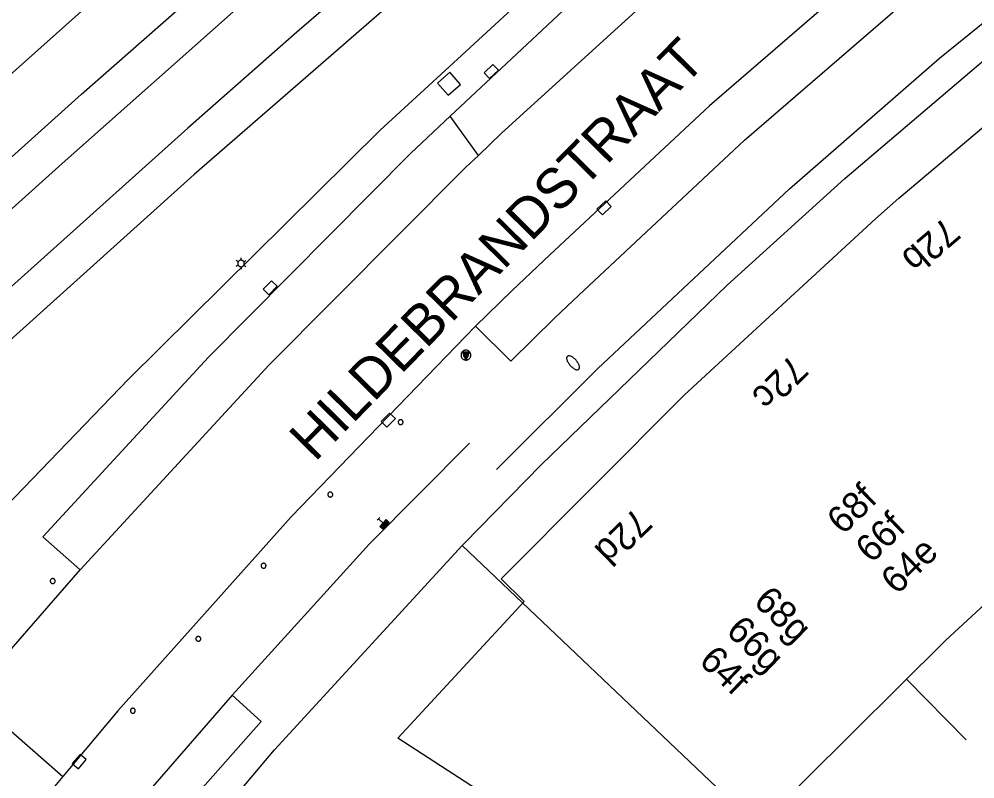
# Model space of a CAD drawing. Extents: x 81065 to 81486, y 452384 to 452681.
# Drawn here: x 81125.76 to 81161.34, y 452398.58 to 452426.85 of the extents above; entities that cross this region are included whole.
import ezdxf

# ---------------------------------------------------------------- set-up
doc = ezdxf.new("R2010")
doc.units = 0
for name, color, linetype in [('B-BH-AL-TOPOGRAFIE_HUISNUMMER-T25', 7, 'Continuous'), ('B-BH-AL-TOPOGRAFIE_STRAATNAAM-S', 7, 'Continuous'), ('B-BH-IE-MEUBILAIR-WEGMEUBILAIR-VERKEERSBORD-S', 7, 'Continuous'), ('B-BH-IE-MEUBILAIR_WEGMEUBILAIR_LICHTMAST-S', 7, 'Continuous'), ('B-BH-IE-MEUBILAIR_WEGMEUBILAIR_PAAL-S', 7, 'Continuous'), ('B-BH-KL-DATA_CAI_KAST-S', 7, 'Continuous'), ('B-BH-KL-WATER_BRANDLEIDING_PUT-S', 7, 'Continuous'), ('B-BH-OG-TERREIN_ERF-GV', 7, 'Continuous'), ('B-BH-OG-TOPOGRAFIE_BEBOUWING-GV', 7, 'Continuous'), ('B-BH-OG-TOPOGRAFIE_BEBOUWING_PANDSCHEIDING-GV', 7, 'Continuous'), ('B-BH-RI-GWA_RIOOLPUT-S', 7, 'Continuous'), ('B-BH-VH-KANTOPSLUITING-GV', 7, 'Continuous'), ('B-SB-OG-WEG_SPOOR_TRAM-G', 7, 'Continuous'), ('B-SRI-KOLK_COMBINATIE-S', 7, 'Continuous')]:
    doc.layers.add(name, color=color, linetype=linetype)

msp = doc.modelspace()

# ---------------------------------------------------------------- linework, layer by layer
at = {"layer": 'B-BH-IE-MEUBILAIR-WEGMEUBILAIR-VERKEERSBORD-S'}
for p, q in [((81142.26, 452414.473), (81142.525, 452414.473)), ((81142.393, 452414.164), (81142.282, 452414.455)), ((81142.282, 452414.455), (81142.498, 452414.455)), ((81142.309, 452414.437), (81142.47, 452414.437)), ((81142.394, 452414.213), (81142.309, 452414.437)), ((81142.395, 452414.262), (81142.335, 452414.418)), ((81142.335, 452414.418), (81142.442, 452414.418)), ((81142.396, 452414.311), (81142.362, 452414.4)), ((81142.362, 452414.4), (81142.414, 452414.4)), ((81142.397, 452414.359), (81142.388, 452414.382)), ((81142.525, 452414.473), (81142.393, 452414.164)), ((81142.498, 452414.455), (81142.394, 452414.213)), ((81142.47, 452414.437), (81142.395, 452414.262)), ((81142.442, 452414.418), (81142.396, 452414.311)), ((81142.414, 452414.4), (81142.397, 452414.359))]:
    msp.add_line(p, q, dxfattribs=at)
msp.add_lwpolyline([(81142.21, 452414.347), (81142.211, 452414.328), (81142.214, 452414.309), (81142.219, 452414.29), (81142.226, 452414.272), (81142.234, 452414.255), (81142.245, 452414.239), (81142.257, 452414.224), (81142.27, 452414.211), (81142.285, 452414.199), (81142.301, 452414.188), (81142.318, 452414.18), (81142.336, 452414.173), (81142.355, 452414.168), (81142.374, 452414.165), (81142.393, 452414.164), (81142.412, 452414.165), (81142.431, 452414.168), (81142.45, 452414.173), (81142.467, 452414.18), (81142.484, 452414.188), (81142.501, 452414.199), (81142.515, 452414.211), (81142.529, 452414.224), (81142.541, 452414.239), (81142.551, 452414.255), (81142.56, 452414.272), (81142.567, 452414.29), (81142.572, 452414.309), (81142.575, 452414.328), (81142.576, 452414.347), (81142.575, 452414.366), (81142.572, 452414.385), (81142.567, 452414.404), (81142.56, 452414.421), (81142.551, 452414.438), (81142.541, 452414.455), (81142.529, 452414.469), (81142.515, 452414.483), (81142.501, 452414.495), (81142.484, 452414.505), (81142.467, 452414.514), (81142.45, 452414.521), (81142.431, 452414.526), (81142.412, 452414.529), (81142.393, 452414.53), (81142.374, 452414.529), (81142.355, 452414.526), (81142.336, 452414.521), (81142.318, 452414.514), (81142.301, 452414.505), (81142.285, 452414.495), (81142.27, 452414.483), (81142.257, 452414.469), (81142.245, 452414.455), (81142.234, 452414.438), (81142.226, 452414.421), (81142.219, 452414.404), (81142.214, 452414.385), (81142.211, 452414.366), (81142.21, 452414.347)], dxfattribs=at)
at = {"layer": 'B-BH-IE-MEUBILAIR_WEGMEUBILAIR_LICHTMAST-S'}
for p, q in [((81133.915, 452417.818), (81133.836, 452417.864)), ((81134.021, 452417.879), (81134.021, 452417.971)), ((81134.126, 452417.818), (81134.206, 452417.864)), ((81133.915, 452417.696), (81133.836, 452417.65)), ((81134.021, 452417.635), (81134.021, 452417.543)), ((81134.126, 452417.696), (81134.206, 452417.65))]:
    msp.add_line(p, q, dxfattribs=at)
msp.add_lwpolyline([(81133.899, 452417.757), (81133.9, 452417.744), (81133.901, 452417.731), (81133.905, 452417.719), (81133.909, 452417.707), (81133.915, 452417.696), (81133.922, 452417.685), (81133.93, 452417.675), (81133.939, 452417.666), (81133.949, 452417.658), (81133.96, 452417.651), (81133.971, 452417.645), (81133.983, 452417.641), (81133.996, 452417.637), (81134.008, 452417.636), (81134.021, 452417.635), (81134.034, 452417.636), (81134.046, 452417.637), (81134.059, 452417.641), (81134.071, 452417.645), (81134.082, 452417.651), (81134.093, 452417.658), (81134.103, 452417.666), (81134.112, 452417.675), (81134.12, 452417.685), (81134.127, 452417.696), (81134.132, 452417.707), (81134.137, 452417.719), (81134.14, 452417.731), (81134.142, 452417.744), (81134.143, 452417.757), (81134.142, 452417.77), (81134.14, 452417.782), (81134.137, 452417.795), (81134.132, 452417.807), (81134.127, 452417.818), (81134.12, 452417.829), (81134.112, 452417.839), (81134.103, 452417.848), (81134.093, 452417.856), (81134.082, 452417.863), (81134.071, 452417.868), (81134.059, 452417.873), (81134.046, 452417.876), (81134.034, 452417.878), (81134.021, 452417.879), (81134.008, 452417.878), (81133.995, 452417.876), (81133.983, 452417.873), (81133.971, 452417.868), (81133.96, 452417.863), (81133.949, 452417.856), (81133.939, 452417.848), (81133.93, 452417.839), (81133.922, 452417.829), (81133.915, 452417.818), (81133.909, 452417.807), (81133.905, 452417.795), (81133.901, 452417.782), (81133.9, 452417.77), (81133.899, 452417.757)], dxfattribs=at)
at = {"layer": 'B-BH-IE-MEUBILAIR_WEGMEUBILAIR_PAAL-S'}
for points in [[(81142.301, 452414.347), (81142.302, 452414.337), (81142.303, 452414.328), (81142.306, 452414.318), (81142.309, 452414.309), (81142.313, 452414.301), (81142.319, 452414.293), (81142.325, 452414.285), (81142.331, 452414.279), (81142.339, 452414.273), (81142.347, 452414.267), (81142.356, 452414.263), (81142.364, 452414.26), (81142.374, 452414.257), (81142.383, 452414.256), (81142.393, 452414.255), (81142.402, 452414.256), (81142.412, 452414.257), (81142.421, 452414.26), (81142.43, 452414.263), (81142.439, 452414.267), (81142.447, 452414.273), (81142.454, 452414.279), (81142.461, 452414.285), (81142.467, 452414.293), (81142.472, 452414.301), (81142.476, 452414.309), (81142.48, 452414.318), (81142.482, 452414.328), (81142.484, 452414.337), (81142.484, 452414.347), (81142.484, 452414.356), (81142.482, 452414.366), (81142.48, 452414.375), (81142.476, 452414.384), (81142.472, 452414.392), (81142.467, 452414.4), (81142.461, 452414.408), (81142.454, 452414.415), (81142.447, 452414.421), (81142.439, 452414.426), (81142.43, 452414.43), (81142.421, 452414.434), (81142.412, 452414.436), (81142.402, 452414.438), (81142.393, 452414.438), (81142.383, 452414.438), (81142.374, 452414.436), (81142.364, 452414.434), (81142.356, 452414.43), (81142.347, 452414.426), (81142.339, 452414.421), (81142.331, 452414.415), (81142.325, 452414.408), (81142.319, 452414.4), (81142.313, 452414.392), (81142.309, 452414.384), (81142.306, 452414.375), (81142.303, 452414.366), (81142.302, 452414.356), (81142.301, 452414.347)], [(81139.871, 452411.854), (81139.872, 452411.844), (81139.873, 452411.835), (81139.876, 452411.825), (81139.879, 452411.816), (81139.883, 452411.808), (81139.889, 452411.8), (81139.895, 452411.792), (81139.901, 452411.786), (81139.909, 452411.78), (81139.917, 452411.774), (81139.926, 452411.77), (81139.934, 452411.767), (81139.944, 452411.764), (81139.953, 452411.763), (81139.963, 452411.762), (81139.972, 452411.763), (81139.982, 452411.764), (81139.991, 452411.767), (81140, 452411.77), (81140.009, 452411.774), (81140.017, 452411.78), (81140.024, 452411.786), (81140.031, 452411.792), (81140.037, 452411.8), (81140.042, 452411.808), (81140.046, 452411.816), (81140.05, 452411.825), (81140.052, 452411.835), (81140.054, 452411.844), (81140.054, 452411.854), (81140.054, 452411.863), (81140.052, 452411.873), (81140.05, 452411.882), (81140.046, 452411.891), (81140.042, 452411.899), (81140.037, 452411.907), (81140.031, 452411.915), (81140.024, 452411.922), (81140.017, 452411.928), (81140.009, 452411.933), (81140, 452411.937), (81139.991, 452411.941), (81139.982, 452411.943), (81139.972, 452411.945), (81139.963, 452411.945), (81139.953, 452411.945), (81139.944, 452411.943), (81139.934, 452411.941), (81139.926, 452411.937), (81139.917, 452411.933), (81139.909, 452411.928), (81139.901, 452411.922), (81139.895, 452411.915), (81139.889, 452411.907), (81139.883, 452411.899), (81139.879, 452411.891), (81139.876, 452411.882), (81139.873, 452411.873), (81139.872, 452411.863), (81139.871, 452411.854)], [(81137.252, 452409.158), (81137.253, 452409.148), (81137.254, 452409.139), (81137.257, 452409.129), (81137.26, 452409.12), (81137.264, 452409.112), (81137.27, 452409.104), (81137.276, 452409.096), (81137.282, 452409.09), (81137.29, 452409.084), (81137.298, 452409.078), (81137.307, 452409.074), (81137.315, 452409.071), (81137.325, 452409.068), (81137.334, 452409.067), (81137.344, 452409.066), (81137.353, 452409.067), (81137.363, 452409.068), (81137.372, 452409.071), (81137.381, 452409.074), (81137.39, 452409.078), (81137.398, 452409.084), (81137.405, 452409.09), (81137.412, 452409.096), (81137.418, 452409.104), (81137.423, 452409.112), (81137.427, 452409.12), (81137.431, 452409.129), (81137.433, 452409.139), (81137.435, 452409.148), (81137.435, 452409.158), (81137.435, 452409.167), (81137.433, 452409.177), (81137.431, 452409.186), (81137.427, 452409.195), (81137.423, 452409.203), (81137.418, 452409.211), (81137.412, 452409.219), (81137.405, 452409.226), (81137.398, 452409.232), (81137.39, 452409.237), (81137.381, 452409.241), (81137.372, 452409.245), (81137.363, 452409.247), (81137.353, 452409.249), (81137.344, 452409.249), (81137.334, 452409.249), (81137.325, 452409.247), (81137.315, 452409.245), (81137.307, 452409.241), (81137.298, 452409.237), (81137.29, 452409.232), (81137.282, 452409.226), (81137.276, 452409.219), (81137.27, 452409.211), (81137.264, 452409.203), (81137.26, 452409.195), (81137.257, 452409.186), (81137.254, 452409.177), (81137.253, 452409.167), (81137.252, 452409.158)], [(81134.769, 452406.511), (81134.77, 452406.501), (81134.771, 452406.492), (81134.774, 452406.482), (81134.777, 452406.473), (81134.781, 452406.465), (81134.787, 452406.457), (81134.793, 452406.449), (81134.799, 452406.443), (81134.807, 452406.437), (81134.815, 452406.431), (81134.824, 452406.427), (81134.832, 452406.424), (81134.842, 452406.421), (81134.851, 452406.42), (81134.861, 452406.419), (81134.87, 452406.42), (81134.88, 452406.421), (81134.889, 452406.424), (81134.898, 452406.427), (81134.907, 452406.431), (81134.915, 452406.437), (81134.922, 452406.443), (81134.929, 452406.449), (81134.935, 452406.457), (81134.94, 452406.465), (81134.944, 452406.473), (81134.948, 452406.482), (81134.95, 452406.492), (81134.952, 452406.501), (81134.952, 452406.511), (81134.952, 452406.52), (81134.95, 452406.53), (81134.948, 452406.539), (81134.944, 452406.548), (81134.94, 452406.556), (81134.935, 452406.564), (81134.929, 452406.572), (81134.922, 452406.579), (81134.915, 452406.585), (81134.907, 452406.59), (81134.898, 452406.594), (81134.889, 452406.598), (81134.88, 452406.6), (81134.87, 452406.602), (81134.861, 452406.602), (81134.851, 452406.602), (81134.842, 452406.6), (81134.832, 452406.598), (81134.824, 452406.594), (81134.815, 452406.59), (81134.807, 452406.585), (81134.799, 452406.579), (81134.793, 452406.572), (81134.787, 452406.564), (81134.781, 452406.556), (81134.777, 452406.548), (81134.774, 452406.539), (81134.771, 452406.53), (81134.77, 452406.52), (81134.769, 452406.511)], [(81126.92, 452405.939), (81126.921, 452405.929), (81126.922, 452405.92), (81126.925, 452405.91), (81126.928, 452405.901), (81126.932, 452405.893), (81126.938, 452405.885), (81126.944, 452405.877), (81126.95, 452405.871), (81126.958, 452405.865), (81126.966, 452405.859), (81126.975, 452405.855), (81126.983, 452405.852), (81126.993, 452405.849), (81127.002, 452405.848), (81127.012, 452405.847), (81127.021, 452405.848), (81127.031, 452405.849), (81127.04, 452405.852), (81127.049, 452405.855), (81127.058, 452405.859), (81127.066, 452405.865), (81127.073, 452405.871), (81127.08, 452405.877), (81127.086, 452405.885), (81127.091, 452405.893), (81127.095, 452405.901), (81127.099, 452405.91), (81127.101, 452405.92), (81127.103, 452405.929), (81127.103, 452405.939), (81127.103, 452405.948), (81127.101, 452405.958), (81127.099, 452405.967), (81127.095, 452405.976), (81127.091, 452405.984), (81127.086, 452405.992), (81127.08, 452406), (81127.073, 452406.007), (81127.066, 452406.013), (81127.058, 452406.018), (81127.049, 452406.022), (81127.04, 452406.026), (81127.031, 452406.028), (81127.021, 452406.03), (81127.012, 452406.03), (81127.002, 452406.03), (81126.993, 452406.028), (81126.983, 452406.026), (81126.975, 452406.022), (81126.966, 452406.018), (81126.958, 452406.013), (81126.95, 452406.007), (81126.944, 452406), (81126.938, 452405.992), (81126.932, 452405.984), (81126.928, 452405.976), (81126.925, 452405.967), (81126.922, 452405.958), (81126.921, 452405.948), (81126.92, 452405.939)], [(81132.34, 452403.79), (81132.341, 452403.78), (81132.342, 452403.771), (81132.345, 452403.761), (81132.348, 452403.752), (81132.352, 452403.744), (81132.358, 452403.736), (81132.364, 452403.728), (81132.37, 452403.722), (81132.378, 452403.716), (81132.386, 452403.71), (81132.395, 452403.706), (81132.403, 452403.703), (81132.413, 452403.7), (81132.422, 452403.699), (81132.432, 452403.698), (81132.441, 452403.699), (81132.451, 452403.7), (81132.46, 452403.703), (81132.469, 452403.706), (81132.478, 452403.71), (81132.486, 452403.716), (81132.493, 452403.722), (81132.5, 452403.728), (81132.506, 452403.736), (81132.511, 452403.744), (81132.515, 452403.752), (81132.519, 452403.761), (81132.521, 452403.771), (81132.523, 452403.78), (81132.523, 452403.79), (81132.523, 452403.799), (81132.521, 452403.809), (81132.519, 452403.818), (81132.515, 452403.827), (81132.511, 452403.835), (81132.506, 452403.843), (81132.5, 452403.851), (81132.493, 452403.858), (81132.486, 452403.864), (81132.478, 452403.869), (81132.469, 452403.873), (81132.46, 452403.877), (81132.451, 452403.879), (81132.441, 452403.881), (81132.432, 452403.881), (81132.422, 452403.881), (81132.413, 452403.879), (81132.403, 452403.877), (81132.395, 452403.873), (81132.386, 452403.869), (81132.378, 452403.864), (81132.37, 452403.858), (81132.364, 452403.851), (81132.358, 452403.843), (81132.352, 452403.835), (81132.348, 452403.827), (81132.345, 452403.818), (81132.342, 452403.809), (81132.341, 452403.799), (81132.34, 452403.79)], [(81129.903, 452401.112), (81129.904, 452401.102), (81129.905, 452401.093), (81129.908, 452401.083), (81129.911, 452401.074), (81129.915, 452401.066), (81129.921, 452401.058), (81129.927, 452401.05), (81129.933, 452401.044), (81129.941, 452401.038), (81129.949, 452401.032), (81129.958, 452401.028), (81129.966, 452401.025), (81129.976, 452401.022), (81129.985, 452401.021), (81129.995, 452401.02), (81130.004, 452401.021), (81130.014, 452401.022), (81130.023, 452401.025), (81130.032, 452401.028), (81130.041, 452401.032), (81130.049, 452401.038), (81130.056, 452401.044), (81130.063, 452401.05), (81130.069, 452401.058), (81130.074, 452401.066), (81130.078, 452401.074), (81130.082, 452401.083), (81130.084, 452401.093), (81130.086, 452401.102), (81130.086, 452401.112), (81130.086, 452401.121), (81130.084, 452401.131), (81130.082, 452401.14), (81130.078, 452401.149), (81130.074, 452401.157), (81130.069, 452401.165), (81130.063, 452401.173), (81130.056, 452401.18), (81130.049, 452401.186), (81130.041, 452401.191), (81130.032, 452401.195), (81130.023, 452401.199), (81130.014, 452401.201), (81130.004, 452401.203), (81129.995, 452401.203), (81129.985, 452401.203), (81129.976, 452401.201), (81129.966, 452401.199), (81129.958, 452401.195), (81129.949, 452401.191), (81129.941, 452401.186), (81129.933, 452401.18), (81129.927, 452401.173), (81129.921, 452401.165), (81129.915, 452401.157), (81129.911, 452401.149), (81129.908, 452401.14), (81129.905, 452401.131), (81129.904, 452401.121), (81129.903, 452401.112)]]:
    msp.add_lwpolyline(points, dxfattribs=at)
at = {"layer": 'B-BH-KL-DATA_CAI_KAST-S'}
for p, q in [((81139.094, 452408.199), (81139.188, 452408.3)), ((81139.142, 452408.25), (81139.308, 452408.095)), ((81139.189, 452407.967), (81139.427, 452408.224)), ((81139.22, 452407.964), (81139.433, 452408.194)), ((81139.427, 452408.224), (81139.537, 452408.123)), ((81139.433, 452408.194), (81139.506, 452408.127)), ((81139.299, 452407.866), (81139.189, 452407.967)), ((81139.293, 452407.896), (81139.22, 452407.964)), ((81139.251, 452407.96), (81139.439, 452408.164)), ((81139.288, 452407.927), (81139.251, 452407.96)), ((81139.282, 452407.957), (81139.445, 452408.134)), ((81139.288, 452407.927), (81139.475, 452408.13)), ((81139.293, 452407.896), (81139.506, 452408.127)), ((81139.537, 452408.123), (81139.299, 452407.866)), ((81139.439, 452408.164), (81139.475, 452408.13))]:
    msp.add_line(p, q, dxfattribs=at)
at = {"layer": 'B-BH-KL-WATER_BRANDLEIDING_PUT-S'}
msp.add_lwpolyline([(81146.49, 452414.157), (81146.467, 452414.182), (81146.443, 452414.205), (81146.419, 452414.227), (81146.394, 452414.247), (81146.369, 452414.265), (81146.344, 452414.28), (81146.32, 452414.294), (81146.296, 452414.304), (81146.273, 452414.312), (81146.251, 452414.318), (81146.231, 452414.32), (81146.212, 452414.32), (81146.196, 452414.316), (81146.181, 452414.31), (81146.168, 452414.302), (81146.158, 452414.29), (81146.15, 452414.276), (81146.145, 452414.26), (81146.142, 452414.242), (81146.142, 452414.221), (81146.145, 452414.199), (81146.15, 452414.175), (81146.157, 452414.15), (81146.167, 452414.124), (81146.18, 452414.098), (81146.194, 452414.071), (81146.211, 452414.044), (81146.23, 452414.017), (81146.25, 452413.99), (81146.271, 452413.965), (81146.294, 452413.94), (81146.318, 452413.917), (81146.342, 452413.895), (81146.367, 452413.875), (81146.392, 452413.857), (81146.417, 452413.841), (81146.442, 452413.828), (81146.466, 452413.818), (81146.488, 452413.81), (81146.51, 452413.804), (81146.53, 452413.802), (81146.549, 452413.802), (81146.566, 452413.806), (81146.581, 452413.812), (81146.593, 452413.82), (81146.603, 452413.832), (81146.611, 452413.846), (81146.616, 452413.862), (81146.619, 452413.88), (81146.619, 452413.901), (81146.617, 452413.923), (81146.612, 452413.947), (81146.604, 452413.972), (81146.594, 452413.997), (81146.581, 452414.024), (81146.567, 452414.051), (81146.55, 452414.078), (81146.532, 452414.105), (81146.511, 452414.132), (81146.49, 452414.157)], dxfattribs=at)
at = {"layer": 'B-BH-OG-TERREIN_ERF-GV'}
msp.add_line((81158.795, 452402.292), (81161.008, 452400.033), dxfattribs=at)
at = {"layer": 'B-BH-OG-TOPOGRAFIE_BEBOUWING-GV'}
for points in [[(81126.018, 452388.532), (81127.195, 452390.075), (81135.264, 452399.653), (81142.254, 452407.263), (81142.332, 452407.331), (81145.191, 452410.261), (81152.12, 452416.954), (81156.495, 452420.925), (81163.982, 452427.288), (81169.073, 452431.334), (81177.002, 452437.212), (81179.582, 452438.967)], [(81153.251, 452396.796), (81151.969, 452398.03), (81148.503, 452394.479), (81139.858, 452400.091), (81144.562, 452405.184), (81143.704, 452406.025), (81150.532, 452412.867), (81157.636, 452419.422), (81158.509, 452420.19), (81166.091, 452426.576), (81171.032, 452430.467), (81180.823, 452437.684), (81181.948, 452438.481)], [(81180.883, 452421.217), (81173.621, 452415.514), (81166.038, 452409.069), (81160.256, 452403.741), (81153.266, 452396.81), (81153.251, 452396.796)]]:
    msp.add_lwpolyline(points, dxfattribs=at)
at = {"layer": 'B-BH-OG-TOPOGRAFIE_BEBOUWING_PANDSCHEIDING-GV'}
msp.add_line((81142.254, 452407.263), (81151.969, 452398.03), dxfattribs=at)
at = {"layer": 'B-BH-RI-GWA_RIOOLPUT-S'}
for p, q in [((81141.792, 452424.873), (81141.334, 452424.474)), ((81142.19, 452424.415), (81141.792, 452424.873)), ((81141.334, 452424.474), (81141.732, 452424.016)), ((81141.732, 452424.016), (81142.19, 452424.415))]:
    msp.add_line(p, q, dxfattribs=at)
at = {"layer": 'B-BH-VH-KANTOPSLUITING-GV'}
for p, q in [((81131.086, 452429.833), (81124.643, 452424.084)), ((81142.857, 452421.78), (81141.808, 452423.239)), ((81123.96, 452401.661), (81127.389, 452398.664))]:
    msp.add_line(p, q, dxfattribs=at)
for points in [[(81140.996, 452424.369), (81146.104, 452429.072), (81153.228, 452435.084), (81161.305, 452441.447), (81162.668, 452442.441)], [(81164.068, 452442.154), (81163.029, 452441.387), (81154.74, 452434.776), (81153.97, 452434.135), (81146.004, 452427.162), (81141.808, 452423.239)], [(81142.857, 452421.78), (81143.721, 452422.609), (81151.159, 452429.38), (81158.861, 452435.849), (81160.95, 452437.516), (81166.505, 452441.653)], [(81172.398, 452440.443), (81167.9, 452437.209), (81160.559, 452431.438), (81159.067, 452430.202), (81151.454, 452423.628), (81145.52, 452418.076)], [(81146.597, 452416.577), (81152.757, 452422.352), (81160.08, 452428.668), (81160.699, 452429.18), (81168.493, 452435.353), (81174.802, 452439.949)], [(81143.534, 452410.094), (81147.299, 452413.851), (81154.435, 452420.535), (81160.019, 452425.401), (81167.617, 452431.556), (81172.763, 452435.453), (81178.135, 452439.264)], [(81117.537, 452400.177), (81119.063, 452401.963), (81125.277, 452408.727), (81129.835, 452413.447), (81139.202, 452422.718), (81140.996, 452424.369)], [(81141.808, 452423.239), (81140.341, 452421.868), (81132.815, 452414.269), (81126.639, 452407.585), (81128.031, 452406.358)], [(81128.031, 452406.358), (81135.062, 452413.979), (81142.381, 452421.324), (81142.857, 452421.78)], [(81145.52, 452418.076), (81144.109, 452416.756), (81142.75, 452415.423)], [(81142.75, 452415.423), (81144.064, 452414.123), (81145.701, 452415.738), (81146.597, 452416.577)], [(81142.75, 452415.423), (81135.885, 452408.332), (81129.439, 452401.115), (81127.389, 452398.664), (81123.349, 452393.832), (81121.926, 452391.977)], [(81133.697, 452401.686), (81138.809, 452407.323), (81142.531, 452411.075)], [(81118.394, 452394.815), (81120.717, 452397.671), (81124.301, 452402.08), (81128.031, 452406.358)], [(81133.697, 452401.686), (81130.407, 452397.904), (81131.452, 452396.961)], [(81131.452, 452396.961), (81134.766, 452400.715), (81133.697, 452401.686)]]:
    msp.add_lwpolyline(points, dxfattribs=at)
at = {"layer": 'B-SB-OG-WEG_SPOOR_TRAM-G'}
for points in [[(81157.567, 452443.489), (81157.429, 452443.392), (81153.04, 452440.159), (81148.717, 452436.839), (81144.461, 452433.433), (81141.79, 452431.226), (81141.363, 452430.872), (81140.938, 452430.516), (81140.726, 452430.337), (81139.039, 452428.897), (81138.407, 452428.356), (81137.777, 452427.814), (81137.253, 452427.361), (81136.102, 452426.361), (81135.476, 452425.815), (81134.539, 452424.993), (81133.915, 452424.443), (81133.291, 452423.894), (81132.047, 452422.791)], [(81159.493, 452443.093), (81158.269, 452442.229), (81153.904, 452439.013), (81149.605, 452435.712), (81142.074, 452429.595), (81132.278, 452421.075), (81111.932, 452402.757)], [(81091.566, 452395.787), (81093.82, 452396.784), (81096.032, 452397.873), (81098.197, 452399.05), (81100.313, 452400.314), (81102.376, 452401.662), (81104.383, 452403.094), (81108.058, 452406.052), (81128.086, 452424.061), (81138.732, 452433.407), (81144.254, 452437.992)], [(81073.376, 452389.882), (81075.079, 452390.039), (81077.581, 452390.371), (81080.067, 452390.805), (81082.533, 452391.34), (81084.975, 452391.974), (81087.39, 452392.707), (81089.773, 452393.538), (81092.121, 452394.464), (81094.428, 452395.485), (81096.693, 452396.599), (81098.91, 452397.805), (81101.076, 452399.099), (81103.188, 452400.48), (81105.243, 452401.945), (81109.072, 452405.032), (81127.365, 452421.484), (81136.586, 452429.669)], [(81132.047, 452422.791), (81108.447, 452401.618), (81105.218, 452399.064), (81103.151, 452397.608), (81101.023, 452396.242), (81098.839, 452394.968), (81096.602, 452393.789), (81094.317, 452392.706), (81091.988, 452391.723), (81089.619, 452390.839), (81087.214, 452390.059), (81084.778, 452389.381), (81083.906, 452389.179)]]:
    msp.add_lwpolyline(points, dxfattribs=at)
at = {"layer": 'B-SRI-KOLK_COMBINATIE-S'}
for p, q in [((81143.398, 452425.165), (81143.071, 452424.859)), ((81143.272, 452424.644), (81143.599, 452424.949)), ((81143.599, 452424.949), (81143.398, 452425.165)), ((81143.071, 452424.859), (81143.272, 452424.644)), ((81147.596, 452420.087), (81147.27, 452419.78)), ((81147.798, 452419.873), (81147.596, 452420.087)), ((81147.27, 452419.78), (81147.472, 452419.565)), ((81147.472, 452419.565), (81147.798, 452419.873)), ((81135.156, 452417.116), (81134.842, 452416.796)), ((81135.367, 452416.909), (81135.156, 452417.116)), ((81134.842, 452416.796), (81135.053, 452416.589)), ((81135.053, 452416.589), (81135.367, 452416.909)), ((81139.553, 452412.193), (81139.241, 452411.872)), ((81139.765, 452411.987), (81139.553, 452412.193)), ((81139.241, 452411.872), (81139.452, 452411.666)), ((81139.452, 452411.666), (81139.765, 452411.987)), ((81128.032, 452399.489), (81127.741, 452399.148)), ((81127.966, 452398.956), (81128.256, 452399.297)), ((81128.256, 452399.297), (81128.032, 452399.489)), ((81127.741, 452399.148), (81127.966, 452398.956))]:
    msp.add_line(p, q, dxfattribs=at)

# ---------------------------------------------------------------- texts
at = {"layer": 'B-BH-AL-TOPOGRAFIE_HUISNUMMER-T25'}
for s, rotation, p in [('72b', 220.5817, (81160.228, 452419.522)), ('72c', 224.4246, (81154.512, 452414.411)), ('68f', 44.1674, (81156.429, 452407.627)), ('72d', 224.4246, (81148.701, 452408.717)), ('66f', 44.1674, (81157.491, 452406.568)), ('64e', 44.1674, (81158.437, 452405.396)), ('68g', 316.1728, (81153.054, 452405.122)), ('66g', 316.1728, (81152.032, 452404.024)), ('64f', 316.1728, (81151.025, 452402.911))]:
    msp.add_text(s, height=1, rotation=rotation, dxfattribs=at).set_placement(p)
at = {"layer": 'B-BH-AL-TOPOGRAFIE_STRAATNAAM-S'}
msp.add_text('HILDEBRANDSTRAAT', height=1.5, rotation=45.5045, dxfattribs=at).set_placement((81136.769, 452410.345))

doc.saveas('drawing.dxf')
